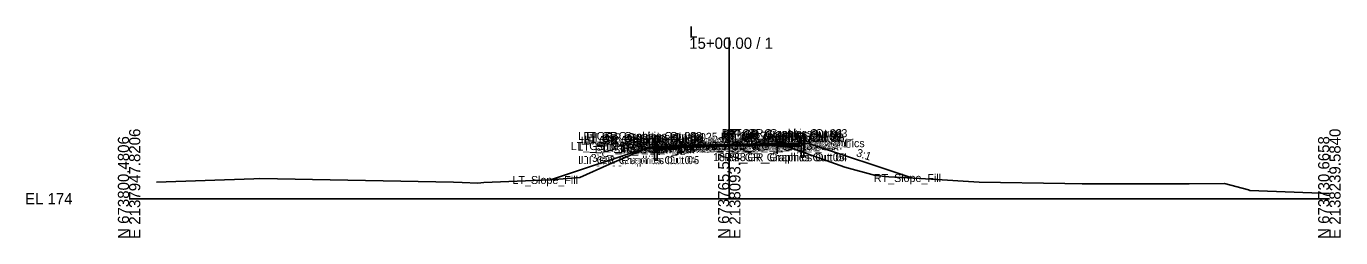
# Model space of a CAD drawing. Extents: x -26 to 5503, y -10 to 7033.
# Drawn here: x -25.7 to 302.8, y 5990.3 to 6043 of the extents above; entities that cross this region are included whole.
import ezdxf

# ---------------------------------------------------------------- set-up
doc = ezdxf.new("R2010")
doc.units = 0
for name, color, linetype in [('Default', 7, 'Continuous'), ('Exist CMT Pavement', 7, 'Continuous'), ('Exist Cross Section Cell', 7, 'Continuous'), ('Exist XS Center Line Elevation Label', 7, 'Continuous'), ('Exist XS Ground Line', 7, 'Continuous'), ('Prop CMT Guardrail Graphics', 7, 'Continuous'), ('Prop CMT Pvmt Course 1', 7, 'Continuous'), ('Prop CMT Pvmt Course 1 Wedge', 7, 'Continuous'), ('Prop CMT Pvmt Course 2', 7, 'Continuous'), ('Prop CMT Pvmt Course 2 Wedge', 7, 'Continuous'), ('Prop CMT Pvmt Course 3', 7, 'Continuous'), ('Prop CMT Pvmt Course 3 Wedge', 7, 'Continuous'), ('Prop CMT Pvmt Surface', 7, 'Continuous'), ('Prop CMT Pvmt Surface Shoulder', 7, 'Continuous'), ('Prop CMT Pvmt Wedge Surface 1', 7, 'Continuous'), ('Prop CMT Pvmt Wedge Surface 2', 7, 'Continuous'), ('Prop CMT Pvmt Wedge Surface 3', 7, 'Continuous'), ('Prop CMT Shld Paved Course 1', 7, 'Continuous'), ('Prop CMT Shld Paved Course 2', 7, 'Continuous'), ('Prop CMT Shld Paved Course 3', 7, 'Continuous'), ('Prop CMT Slope Grass', 7, 'Continuous'), ('Prop CMT Subgrade Earthwork', 7, 'Continuous'), ('Prop XS Earthwork Shape', 7, 'Continuous'), ('Prop XS EOT Tick Mark', 7, 'Continuous'), ('Prop XS SE Text', 7, 'Continuous'), ('Prop XS Side Slope Text', 7, 'Continuous'), ('Prop XS Wedging', 7, 'Continuous')]:
    doc.layers.add(name, color=color, linetype=linetype)

msp = doc.modelspace()

# ---------------------------------------------------------------- linework, layer by layer
at = {"layer": 'Exist CMT Pavement'}
for points in [[(150, 6013.38), (148.67, 6013.38), (144.01, 6013.28), (139.34, 6013.18), (138.01, 6013.15)], [(150, 6013.38), (151.33, 6013.36), (155.99, 6013.28), (160.66, 6013.2), (161.99, 6013.16)]]:
    msp.add_lwpolyline(points, dxfattribs=at)
at = {"layer": 'Exist Cross Section Cell'}
for p, q in [((150, 6000), (150, 6040.18)), ((0, 6000), (150, 6000)), ((150, 6000), (300, 6000))]:
    msp.add_line(p, q, dxfattribs=at)
at = {"layer": 'Exist XS Ground Line'}
for p, q in [((120.11, 6008.64), (129.1, 6012.42)), ((129.1, 6012.42), (137, 6013.1)), ((137, 6013.1), (137.61, 6013.15)), ((137.61, 6013.15), (137.99, 6013.15)), ((137.99, 6013.15), (149.49, 6013.39)), ((149.49, 6013.39), (150.08, 6013.38)), ((150.08, 6013.38), (161.74, 6013.18)), ((161.74, 6013.18), (162.14, 6013.15)), ((162.14, 6013.15), (164.92, 6012.85)), ((164.92, 6012.85), (178.87, 6007.87)), ((112.65, 6005.33), (120.11, 6008.64)), ((178.87, 6007.87), (186.59, 6005.82)), ((186.59, 6005.82), (189.93, 6005.5)), ((6.84, 6004.13), (31.16, 6004.98)), ((31.16, 6004.98), (32.65, 6005.04)), ((32.65, 6005.04), (81.11, 6004.15)), ((81.11, 6004.15), (83.24, 6004.02)), ((83.24, 6004.02), (87.16, 6003.86)), ((87.16, 6003.86), (88.63, 6004.09)), ((88.63, 6004.09), (105.34, 6004.68)), ((105.34, 6004.68), (112.65, 6005.33)), ((189.93, 6005.5), (200.54, 6004.91)), ((200.54, 6004.91), (212.48, 6004.12)), ((212.48, 6004.12), (233.91, 6003.78)), ((233.91, 6003.78), (238.19, 6003.73)), ((238.19, 6003.73), (251.77, 6003.71)), ((251.77, 6003.71), (263.89, 6003.72)), ((263.89, 6003.72), (264.96, 6003.74)), ((264.96, 6003.74), (273.79, 6003.78)), ((273.79, 6003.78), (279.76, 6002.23)), ((279.76, 6002.23), (280.09, 6002.06)), ((280.09, 6002.06), (300, 6001.32))]:
    msp.add_line(p, q, dxfattribs=at)
at = {"layer": 'Prop CMT Guardrail Graphics'}
for points in [[(131.35, 6009.64), (131.35, 6015.64)], [(131.35, 6015.64), (132.68, 6015.64), (132.95, 6015.34)], [(168.65, 6016.35), (167.32, 6016.35), (167.05, 6016.06)], [(167.05, 6016.06), (167.32, 6015.77)], [(167.32, 6015.77), (167.05, 6015.48)], [(167.05, 6015.48), (167.32, 6015.19), (167.98, 6015.19)], [(168.65, 6010.35), (168.65, 6016.35)], [(132.95, 6014.76), (132.68, 6014.47), (132.02, 6014.47)], [(132.02, 6014.47), (132.02, 6009.64)], [(132.95, 6015.34), (132.68, 6015.05)], [(132.68, 6015.05), (132.95, 6014.76)], [(167.98, 6015.19), (167.98, 6010.35)], [(132.02, 6009.64), (131.35, 6009.64)], [(167.98, 6010.35), (168.65, 6010.35)]]:
    msp.add_lwpolyline(points, dxfattribs=at)
at = {"layer": 'Prop CMT Pvmt Course 1'}
for points in [[(150, 6013.56), (138, 6013.26)], [(138, 6013.26), (138, 6013.01)], [(138, 6013.01), (138.01, 6013.01)], [(138.01, 6013.14), (150, 6013.44)], [(138.01, 6013.01), (138.01, 6013.14)], [(150, 6013.56), (162, 6013.77)], [(161.99, 6013.64), (150, 6013.44)], [(150, 6013.44), (150, 6013.56)], [(150, 6013.44), (150, 6013.56)], [(161.99, 6013.52), (161.99, 6013.64)], [(162, 6013.52), (161.99, 6013.52)], [(162, 6013.77), (162, 6013.52)]]:
    msp.add_lwpolyline(points, dxfattribs=at)
at = {"layer": 'Prop CMT Pvmt Course 1 Wedge'}
for points in [[(150, 6013.44), (138.01, 6013.14)], [(150, 6013.44), (161.99, 6013.64)]]:
    msp.add_lwpolyline(points, dxfattribs=at)
at = {"layer": 'Prop CMT Pvmt Course 2'}
for points in [[(138.01, 6013.01), (138, 6013.01)], [(138, 6013.01), (138, 6012.8)], [(138, 6012.8), (138.01, 6012.8)], [(138.01, 6012.8), (138.01, 6013.01)]]:
    msp.add_lwpolyline(points, dxfattribs=at)
at = {"layer": 'Prop CMT Pvmt Course 2 Wedge'}
for points in [[(150, 6013.31), (138.01, 6013.01)], [(150, 6013.31), (161.99, 6013.52)]]:
    msp.add_lwpolyline(points, dxfattribs=at)
at = {"layer": 'Prop CMT Pvmt Course 3'}
for points in [[(138.01, 6012.8), (138, 6012.8)], [(138, 6012.8), (138, 6012.47)], [(138, 6012.47), (138.01, 6012.47)], [(138.01, 6012.47), (138.01, 6012.8)], [(161.99, 6013.31), (162, 6013.31)], [(161.99, 6012.98), (161.99, 6013.31)], [(162, 6012.98), (161.99, 6012.98)], [(162, 6013.31), (162, 6012.98)]]:
    msp.add_lwpolyline(points, dxfattribs=at)
at = {"layer": 'Prop CMT Pvmt Course 3 Wedge'}
for points in [[(150, 6013.1), (138.01, 6012.8)], [(150, 6013.1), (161.99, 6013.31)]]:
    msp.add_lwpolyline(points, dxfattribs=at)
at = {"layer": 'Prop CMT Pvmt Surface'}
for points in [[(150, 6013.56), (138, 6013.26)], [(150, 6013.56), (162, 6013.77)]]:
    msp.add_lwpolyline(points, dxfattribs=at)
at = {"layer": 'Prop CMT Pvmt Surface Shoulder'}
for points in [[(138, 6013.26), (132.96, 6013.14)], [(162, 6013.77), (167.04, 6013.85)]]:
    msp.add_lwpolyline(points, dxfattribs=at)
at = {"layer": 'Prop CMT Pvmt Wedge Surface 1'}
for points in [[(138.01, 6013.26), (138, 6013.26)], [(150, 6013.44), (138.01, 6013.14)], [(138.01, 6013.14), (138.01, 6013.26)], [(150, 6013.44), (161.99, 6013.64)], [(161.99, 6013.64), (161.99, 6013.77)], [(161.99, 6013.77), (162, 6013.77)]]:
    msp.add_lwpolyline(points, dxfattribs=at)
at = {"layer": 'Prop CMT Pvmt Wedge Surface 2'}
for points in [[(150, 6013.31), (138.01, 6013.01), (138, 6013.01)], [(138, 6013.01), (138, 6013.26)], [(150, 6013.31), (161.99, 6013.52), (162, 6013.52)], [(162, 6013.52), (162, 6013.77)]]:
    msp.add_lwpolyline(points, dxfattribs=at)
at = {"layer": 'Prop CMT Pvmt Wedge Surface 3'}
for points in [[(138, 6012.8), (138, 6013.26)], [(150, 6013.1), (138.01, 6012.8), (138, 6012.8)], [(150, 6013.1), (161.99, 6013.31), (162, 6013.31)], [(162, 6013.31), (162, 6013.77)]]:
    msp.add_lwpolyline(points, dxfattribs=at)
at = {"layer": 'Prop CMT Shld Paved Course 1'}
for points in [[(138, 6013.26), (132.96, 6013.14), (132.71, 6012.88)], [(132.71, 6012.88), (138, 6013.01)], [(138, 6013.01), (138, 6013.26)], [(162, 6013.77), (167.04, 6013.85), (167.28, 6013.61)], [(162, 6013.52), (162, 6013.77)], [(167.28, 6013.61), (162, 6013.52)]]:
    msp.add_lwpolyline(points, dxfattribs=at)
at = {"layer": 'Prop CMT Shld Paved Course 2'}
for points in [[(138, 6013.01), (132.71, 6012.88), (132.49, 6012.67)], [(132.49, 6012.67), (138, 6012.8)], [(138, 6012.8), (138, 6013.01)], [(162, 6013.52), (167.28, 6013.61), (167.49, 6013.4)], [(162, 6013.31), (162, 6013.52)], [(167.49, 6013.4), (162, 6013.31)]]:
    msp.add_lwpolyline(points, dxfattribs=at)
at = {"layer": 'Prop CMT Shld Paved Course 3'}
for points in [[(132.49, 6012.67), (132.15, 6012.33)], [(132.15, 6012.33), (138, 6012.47)], [(138, 6012.8), (132.49, 6012.67)], [(132.49, 6012.67), (132.49, 6012.67)], [(138, 6012.47), (138, 6012.8)], [(162, 6013.31), (167.49, 6013.4)], [(162, 6012.98), (162, 6013.31)], [(167.82, 6013.07), (162, 6012.98)], [(167.49, 6013.4), (167.49, 6013.4)], [(167.49, 6013.4), (167.82, 6013.07)]]:
    msp.add_lwpolyline(points, dxfattribs=at)
at = {"layer": 'Prop CMT Slope Grass'}
for points in [[(129.95, 6012.9), (105.32, 6004.68)], [(132.95, 6013.14), (129.95, 6012.9)], [(132.96, 6013.14), (132.95, 6013.14)], [(167.04, 6013.85), (167.05, 6013.85)], [(167.05, 6013.85), (170.05, 6013.72)], [(170.05, 6013.72), (195.68, 6005.18)]]:
    msp.add_lwpolyline(points, dxfattribs=at)
at = {"layer": 'Prop CMT Subgrade Earthwork'}
for points in [[(132.15, 6012.33), (131.46, 6013.02)], [(138, 6012.47), (132.15, 6012.33)], [(138.01, 6012.47), (138, 6012.47)], [(138.01, 6012.47), (138.01, 6013.15)], [(161.99, 6012.98), (161.99, 6013.16)], [(161.99, 6012.98), (162, 6012.98)], [(162, 6012.98), (167.82, 6013.07)], [(167.82, 6013.07), (168.53, 6013.79)]]:
    msp.add_lwpolyline(points, dxfattribs=at)
at = {"layer": 'Prop XS Earthwork Shape'}
for points in [[(129.95, 6012.9), (105.32, 6004.68), (112.65, 6005.33), (120.11, 6008.64), (129.1, 6012.42), (131.82, 6012.65), (131.46, 6013.02)], [(138.01, 6012.47), (132.15, 6012.33), (131.82, 6012.65), (137, 6013.1), (137.61, 6013.15), (138.01, 6013.15)], [(150, 6013.38), (148.67, 6013.38), (149.49, 6013.39)], [(160.66, 6013.2), (161.99, 6013.16), (161.74, 6013.18)], [(161.99, 6012.98), (161.99, 6013.16), (162.14, 6013.15), (163.52, 6013)], [(170.05, 6013.72), (195.68, 6005.18), (189.93, 6005.5), (186.59, 6005.82), (178.87, 6007.87), (164.92, 6012.85), (163.52, 6013), (167.82, 6013.07), (168.53, 6013.79)]]:
    msp.add_lwpolyline(points, close=True, dxfattribs=at)
at = {"layer": 'Prop XS EOT Tick Mark'}
for points in [[(138, 6013.26), (138, 6014.26)], [(162, 6013.77), (162, 6014.77)]]:
    msp.add_lwpolyline(points, dxfattribs=at)
at = {"layer": 'Prop XS Wedging'}
for p, q in [((138, 6014.26), (138, 6011.04)), ((162, 6014.77), (162, 6011.2))]:
    msp.add_line(p, q, dxfattribs=at)

# ---------------------------------------------------------------- texts
at = {"layer": 'Default'}
for s, height, p in [('LT_GR_Graphics Out 03', 2, (112.25, 6014.64)), ('LT_GR_Graphics Out 06', 2, (112.87, 6013.47)), ('LT_GR_Graphics Out 02', 2, (113.58, 6014.64)), ('LT_GR_Graphics Out 09', 2, (113.58, 6014.05)), ('LT_GR_Graphics Out 07', 2, (113.58, 6013.47)), ('LT_GR_Graphics Out 08', 2, (113.85, 6013.76)), ('LT_GR_Graphics Out 01', 2, (114.42, 6014.34)), ('RT_GR_Graphics Out 08', 2, (147.9, 6014.48)), ('RT_GR_Graphics Out 02', 2, (148.17, 6015.35)), ('RT_GR_Graphics Out 09', 2, (148.17, 6014.77)), ('RT_GR_Graphics Out 07', 2, (148.17, 6014.19)), ('RT_GR_Graphics Out 01', 2, (148.46, 6015.06)), ('RT_GR_Graphics Out 06', 2, (148.79, 6014.19)), ('RT_GR_Graphics Out 03', 2, (149.5, 6015.35)), ('RT_TM_OEOT', 2, (152.9, 6013.77)), ('LT_GS_OS_GR_Face_Graphics', 2, (110.41, 6012.14)), ('LT_Sub_Trench_Out_DLT', 2, (112.03, 6012.02)), ('LT_Sub_Trench_Out', 2, (116.36, 6011.33)), ('LT_PS3_Shelf_Out', 2, (118.48, 6011.67)), ('LT_GS_OS_CTL', 2, (119.32, 6011.9)), ('LT_PS3_OEOP', 2, (122.73, 6011.67)), ('LT_PS2_OEOP', 2, (122.94, 6011.88)), ('LT_PV_Sub_Tie_Out', 2, (122.96, 6012.15)), ('LT_PS1_OEOP', 2, (123.77, 6012.14)), ('LT_PV1_OEEOP_Null', 2, (124.47, 6012.26)), ('LT_PV_EG_TestPt3', 2, (124.85, 6012.18)), ('LT_PV_OEEOP_EG', 2, (125.55, 6012.15)), ('LT_PV1_OEEOP_W', 2, (125.99, 6012.14)), ('LT_Sub_OEEOP', 2, (127.22, 6011.47)), ('LT_PV2_OEEOP', 2, (127.32, 6012.01)), ('LT_PV3_OEEOP', 2, (127.32, 6011.8)), ('LT_Sub_OEOT', 2, (128.08, 6011.47)), ('LT_PV2_OEOT', 2, (128.17, 6012.01)), ('LT_PV3_OEOT', 2, (128.17, 6011.8)), ('LT_PV1_OEOT', 2, (128.74, 6012.26)), ('LT_TM_OEOT', 2, (128.94, 6013.26)), ('LT_PV_EG_TestPt2', 2, (129.52, 6012.28)), ('LT_PV_EG_TestPt1', 2, (134.75, 6012.38)), ('RT_PV_EG_TestPt1', 2, (137.36, 6012.36)), ('PV_EPGL_EG', 2, (141.24, 6012.38)), ('RT_PV_EG_TestPt2', 2, (141.46, 6012.28)), ('PV2_PGL_W', 2, (142.02, 6012.31)), ('PV3_PGL_W', 2, (142.02, 6012.1)), ('PV1_PGL_W', 2, (142.58, 6012.44)), ('RT_GS_OS_GR_Face_Graphics', 2, (144.46, 6012.85)), ('PV1_PGL', 2, (144.47, 6012.56)), ('RT_PV_EG_TestPt3', 2, (146.12, 6012.2)), ('RT_PV_Sub_Tie_Out', 2, (146.89, 6012.16)), ('RT_PV1_OEEOP_Null', 2, (148.4, 6012.77)), ('RT_Sub_Trench_Out_DLT', 2, (149.05, 6012.79)), ('RT_PV_OEEOP_EG', 2, (149.48, 6012.16)), ('RT_PV1_OEEOP_W', 2, (149.93, 6012.64)), ('RT_Sub_OEEOP', 2, (151.16, 6011.98)), ('RT_PV2_OEEOP', 2, (151.25, 6012.52)), ('RT_PV3_OEEOP', 2, (151.25, 6012.31)), ('RT_Sub_Trench_Out', 2, (151.97, 6012.07)), ('RT_Sub_OEOT', 2, (152.03, 6011.98)), ('RT_PV2_OEOT', 2, (152.13, 6012.52)), ('RT_PV3_OEOT', 2, (152.13, 6012.31)), ('RT_PV1_OEOT', 2, (152.69, 6012.77)), ('RT_PS3_Shelf_Out', 2, (153.42, 6012.4)), ('RT_PS2_OEOP', 2, (157.47, 6012.61)), ('RT_PS3_OEOP', 2, (157.68, 6012.4)), ('RT_PS1_OEOP', 2, (157.79, 6012.85)), ('RT_GS_OS_CTL', 2, (159.37, 6012.72)), ('LT_GR_Graphics Out 04', 2, (112.25, 6008.64)), ('LT_GR_Graphics Out 05', 2, (112.91, 6008.64)), ('RT_GR_Graphics Out 05', 2, (148.83, 6009.35)), ('RT_GR_Graphics Out 04', 2, (149.5, 6009.35)), ('LT_Slope_Fill', 2, (95.84, 6003.68)), ('RT_Slope_Fill', 2, (186.15, 6004.18)), ('-', 0.0001, (0, 6000))]:
    msp.add_text(s, height=height, dxfattribs=at).set_placement(p)
at = {"layer": 'Exist Cross Section Cell'}
for s, p in [('L', (140, 6040.18)), ('15+00.00 / 1', (140, 6037.38)), ('EL 174', (-26, 5998.6))]:
    msp.add_text(s, height=2.8, dxfattribs=at).set_placement(p)
for s, p in [('N 673800.4806', (0, 5990)), ('E 2137947.8206', (2.8, 5990)), ('E 2138093.7023', (152.8, 5990)), ('N 673730.6658', (300, 5990)), ('E 2138239.5840', (302.8, 5990)), ('N 673765.5732', (150, 5990))]:
    msp.add_text(s, height=2.8, rotation=90, dxfattribs=at).set_placement(p)
at = {"layer": 'Exist XS Center Line Elevation Label'}
msp.add_text('187.38', height=2, dxfattribs=at).set_placement((145.96, 6009.38))
at = {"layer": 'Prop XS SE Text'}
for s, rotation, p in [('0.025', 1.4321, (140.48, 6014.33)), ('0.017', 0.9739, (152.67, 6014.61))]:
    msp.add_text(s, height=2, rotation=rotation, dxfattribs=at).set_placement(p)
at = {"layer": 'Prop XS Side Slope Text'}
for rotation, p in [(341.5651, (181.58, 6010.67)), (18.4349, (115.88, 6009))]:
    msp.add_text('3:1', height=2, rotation=rotation, dxfattribs=at).set_placement(p)

doc.saveas('drawing.dxf')
